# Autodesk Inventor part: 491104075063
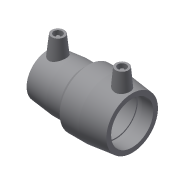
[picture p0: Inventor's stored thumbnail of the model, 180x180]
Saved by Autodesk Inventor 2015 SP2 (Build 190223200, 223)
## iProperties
Created: 2017-06
Part Number: 491104075063
Material: Generic
Description: PLASSON REDUCING COUPLER 75-63
Document SubType Name: Modeling
Designer: KIM
Mass: 54.8237 g
Surface Area: 155.252 cm^2
Volume: 54.8237 cm^3
Density: 1 g/cm^3
Appearance: Default
Author: KIM
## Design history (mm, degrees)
derived "491104.ipt"
feature "Solid1::491104.ipt"
tag "TaggingFeature1"
body "Solid1"
other parameters: "d0" = 126, "d2" = 82, "d3" = 57, "d4" = 34.2, "d5" = 73.8, "d7" = 63, "d8" = 168 deg, "d10" = 22.8, "d11" = 7.6, "d13" = 126, "d14" = 17.6296, "d15" = 57, "d18" = 63, "d19" = 2.85, "d20" = 168 deg, "d22" = 108.92847, "d25" = 135 deg, "d29" = 59, "d30" = 15, "d31" = 47.88, "d34" = 6 deg, "d35" = 15, "d38" = 24.35, "d39" = 5 deg, "d41" = 4, "d42" = 14, "d43" = 0, "d45" = 4, "d46" = 14, "d47" = 0, "d48" = 82, "d49" = 75, "d50" = 98, "d52" = 56.7, "d53" = 26.4, "d54" = 8.8, "d55" = 168 deg, "d56" = 39.6, "d57" = 66, "d58" = 88.2, "d59" = 2.85, "d60" = 135 deg, "d61" = 66, "d62" = 15, "d64" = 4, "d66" = 5 deg, "d67" = 14, "d68" = 0, "d69" = 47.88, "d70" = 82, "d71" = 98, "d73" = 92.12, "d76" = 2.85, "d77" = 168 deg, "d78" = 75, "d79" = 2.85, "d80" = 66, "d81" = 56.7, "d82" = 77.08, "d83" = 120 deg, "d88" = 15, "d89" = 24.75, "d90" = 5 deg, "d92" = 4, "d93" = 14, "d94" = 0, "d95" = 3, "d96" = 0, "d97" = 3, "d98" = 0, "d99" = 16.53, "d100" = 4.1325, "d101" = 74.7676, "d102" = 20 deg, "d103" = 19.14, "d104" = 4.785, "d105" = 89.3564, "d106" = 3.60705, "d107" = 3, "d108" = 0, "d109" = 3, "d110" = 0, "d_1" = 63, "L_" = 126, "L_2" = 57, "D_1" = 82, "A_1" = 59, "d_2" = 12, "L_1" = 66, "d_" = 75, "A_" = 66, "D_" = 98
